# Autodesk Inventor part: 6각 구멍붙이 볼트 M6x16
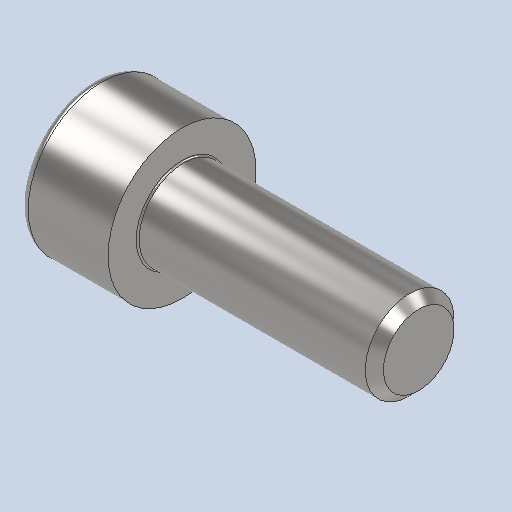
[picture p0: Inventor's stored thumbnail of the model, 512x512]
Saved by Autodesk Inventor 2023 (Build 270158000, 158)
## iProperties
Created: 2025-10
Part Number: 6각 구멍붙이 볼트 M6x16
Material: 강철, 연강
Description: 6각머리 태핑 나사
Document SubType Name: Modeling
Designer: home
Density: 7.85 g/cm^3
Appearance: 기본값
Author: jhkim
Sending System: Autodesk Inventor 2026
Preprocessor: ST-DEVELOPER v20.1
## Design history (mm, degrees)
feature "Solid1"
node "솔리드1"
